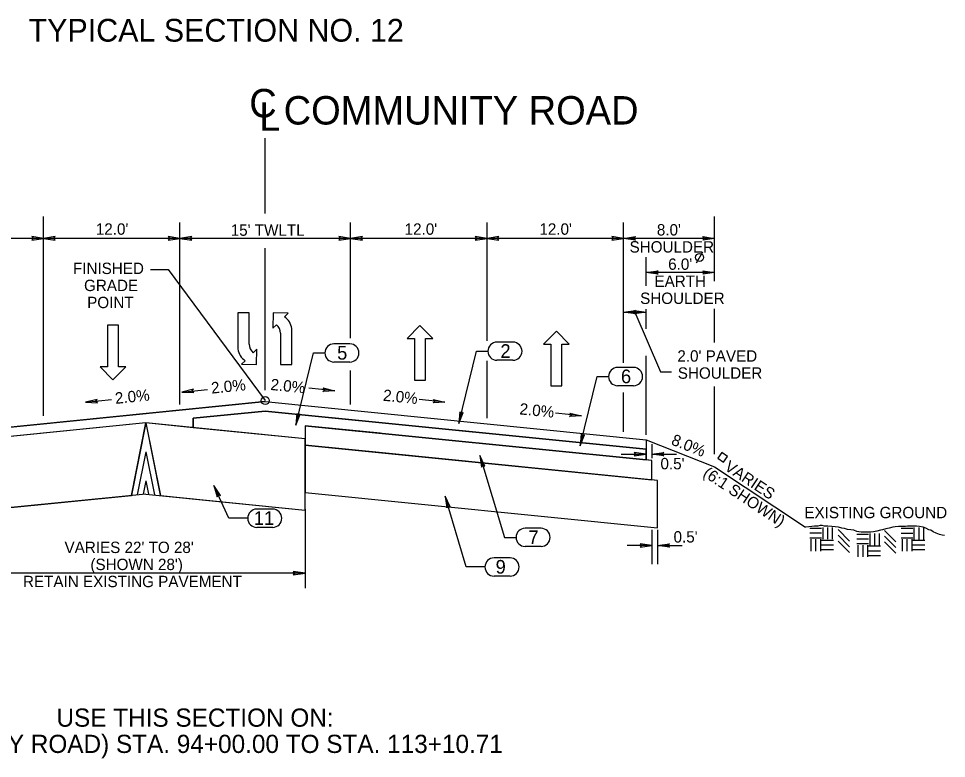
# Model space of a CAD drawing. Extents: x 2003207 to 2014043, y 843846 to 860154.
# Drawn here: x 2013870.6 to 2013952.2, y 844709.9 to 844774.9 of the extents above; entities that cross this region are included whole.
import ezdxf

# ---------------------------------------------------------------- set-up
doc = ezdxf.new("R2010")
doc.units = 0
for name, color, linetype in [('RD_EX_Road', 7, 'Continuous'), ('RD_EX_Road_txCode', 7, 'Continuous'), ('RD_QTY_Base_Course', 7, 'Continuous'), ('RD_QTY_ConcPave', 7, 'Continuous'), ('RD_QTY_Intermediate', 7, 'Continuous'), ('RD_QTY_PermVeg', 7, 'Continuous'), ('RD_QTY_Surf_Course', 7, 'Continuous'), ('RD_TX_Misc1', 7, 'Continuous'), ('RD_TX_Misc2', 7, 'Continuous'), ('RD_TX_TypSect', 7, 'Continuous'), ('RD_XS_ExGround', 7, 'Continuous')]:
    doc.layers.add(name, color=color, linetype=linetype)

msp = doc.modelspace()

# ---------------------------------------------------------------- linework, layer by layer
at = {"layer": 'RD_EX_Road'}
for p, q in [((2013881.821, 844739.393), (2013867.821, 844737.993)), ((2013880.546, 844733.015), (2013881.821, 844739.393)), ((2013881.821, 844739.393), (2013880.55, 844733.037)), ((2013895.821, 844737.993), (2013881.821, 844739.393)), ((2013881.821, 844739.393), (2013883.097, 844733.015)), ((2013881.821, 844739.393), (2013883.093, 844733.037)), ((2013895.821, 844731.743), (2013895.821, 844737.993)), ((2013881.821, 844736.843), (2013881.069, 844733.08)), ((2013881.821, 844736.843), (2013882.574, 844733.08)), ((2013881.821, 844734.293), (2013881.587, 844733.123)), ((2013881.821, 844734.293), (2013882.056, 844733.123)), ((2013881.821, 844733.143), (2013867.821, 844731.743)), ((2013867.821, 844731.743), (2013880.546, 844733.015)), ((2013881.821, 844733.143), (2013895.821, 844731.743)), ((2013883.097, 844733.015), (2013895.821, 844731.743))]:
    msp.add_line(p, q, dxfattribs=at)
at = {"layer": 'RD_EX_Road_txCode'}
msp.add_lwpolyline([(2013932.122, 844736.29), (2013932.622, 844735.959), (2013932.954, 844736.459), (2013932.454, 844736.79)], close=True, dxfattribs=at)
msp.add_circle((2013892.321, 844741.359), 0.35, dxfattribs=at)
at = {"layer": 'RD_QTY_Base_Course'}
for p, q in [((2013902.421, 844738.485), (2013895.821, 844739.145)), ((2013895.821, 844739.145), (2013895.821, 844739.115)), ((2013902.421, 844738.47), (2013902.421, 844738.485)), ((2013926.321, 844736.083), (2013902.421, 844738.47)), ((2013895.821, 844737.441), (2013926.321, 844734.391)), ((2013902.921, 844736.731), (2013895.821, 844737.441)), ((2013895.821, 844737.441), (2013895.821, 844734.676)), ((2013926.821, 844734.341), (2013902.921, 844736.731)), ((2013926.321, 844734.391), (2013926.321, 844736.083)), ((2013895.821, 844734.676), (2013895.821, 844734.192)), ((2013895.821, 844734.192), (2013895.821, 844733.274)), ((2013926.821, 844734.341), (2013926.321, 844734.391)), ((2013926.821, 844730.174), (2013926.821, 844734.341)), ((2013926.821, 844730.174), (2013926.821, 844734.341)), ((2013895.821, 844733.274), (2013926.821, 844730.174)), ((2013895.821, 844733.274), (2013926.821, 844730.174))]:
    msp.add_line(p, q, dxfattribs=at)
msp.add_lwpolyline([(2013895.821, 844739.115), (2013895.821, 844738.282), (2013895.821, 844737.441)], dxfattribs=at)
at = {"layer": 'RD_QTY_ConcPave'}
for p, q in [((2013895.821, 844737.441), (2013926.321, 844734.391)), ((2013926.321, 844736.083), (2013925.821, 844736.145)), ((2013926.321, 844734.391), (2013926.321, 844736.083))]:
    msp.add_line(p, q, dxfattribs=at)
at = {"layer": 'RD_QTY_Intermediate'}
for p, q in [((2013895.821, 844739.145), (2013925.821, 844736.145)), ((2013925.821, 844736.145), (2013925.821, 844737.092))]:
    msp.add_line(p, q, dxfattribs=at)
msp.add_lwpolyline([(2013895.821, 844737.993), (2013885.99, 844738.976), (2013885.99, 844739.809), (2013892.321, 844740.442), (2013895.821, 844740.092), (2013925.821, 844737.092), (2013925.821, 844736.145), (2013895.821, 844739.145)], close=True, dxfattribs=at)
at = {"layer": 'RD_QTY_PermVeg'}
for p, q in [((2013925.821, 844737.926), (2013931.821, 844735.526)), ((2013931.821, 844735.526), (2013939.821, 844730.224))]:
    msp.add_line(p, q, dxfattribs=at)
at = {"layer": 'RD_QTY_Surf_Course'}
for p, q in [((2013892.321, 844741.276), (2013858.821, 844737.926)), ((2013892.321, 844741.276), (2013925.821, 844737.926)), ((2013892.321, 844740.442), (2013925.821, 844737.092)), ((2013925.821, 844737.926), (2013925.821, 844737.092))]:
    msp.add_line(p, q, dxfattribs=at)
msp.add_lwpolyline([(2013858.821, 844737.926), (2013892.321, 844741.276), (2013925.821, 844737.926), (2013925.821, 844737.092), (2013892.321, 844740.442), (2013885.99, 844739.809), (2013885.99, 844738.976), (2013881.821, 844739.393), (2013858.821, 844737.092)], close=True, dxfattribs=at)
at = {"layer": 'RD_TX_Misc2'}
for p, q in [((2013899.759, 844746.35), (2013898.359, 844746.35)), ((2013914.094, 844746.5), (2013912.694, 844746.5)), ((2013899.759, 844744.75), (2013898.359, 844744.75)), ((2013914.094, 844744.9), (2013912.694, 844744.9)), ((2013924.703, 844744.272), (2013923.303, 844744.272)), ((2013924.703, 844742.672), (2013923.303, 844742.672)), ((2013892.975, 844731.819), (2013891.575, 844731.819)), ((2013892.975, 844730.219), (2013891.575, 844730.219)), ((2013916.57, 844730.134), (2013915.17, 844730.134)), ((2013916.57, 844728.534), (2013915.17, 844728.534)), ((2013913.839, 844727.535), (2013912.439, 844727.535)), ((2013913.839, 844725.935), (2013912.439, 844725.935))]:
    msp.add_line(p, q, dxfattribs=at)
for centre, start, end in [((2013898.359, 844745.55), 90, 270), ((2013899.759, 844745.55), 270, 90), ((2013912.694, 844745.7), 90, 270), ((2013914.094, 844745.7), 270, 90), ((2013923.303, 844743.472), 90, 270), ((2013924.703, 844743.472), 270, 90), ((2013891.575, 844731.019), 90, 270), ((2013892.975, 844731.019), 270, 90), ((2013915.17, 844729.334), 90, 270), ((2013916.57, 844729.334), 270, 90), ((2013912.439, 844726.735), 90, 270), ((2013913.839, 844726.735), 270, 90)]:
    msp.add_arc(centre, 0.8, start, end, dxfattribs=at)
at = {"layer": 'RD_TX_TypSect'}
for p, q in [((2013892.321, 844757.819), (2013892.321, 844764.438)), ((2013872.821, 844740.014), (2013872.821, 844757.53)), ((2013884.821, 844741.026), (2013884.821, 844757.013)), ((2013899.821, 844746.845), (2013899.821, 844757.013)), ((2013911.821, 844746.604), (2013911.821, 844757.013)), ((2013923.821, 844744.965), (2013923.821, 844757.013)), ((2013923.821, 844744.678), (2013923.821, 844757.013)), ((2013931.821, 844751.872), (2013931.821, 844757.53)), ((2013872.821, 844755.623), (2013860.821, 844755.623)), ((2013884.821, 844755.623), (2013872.821, 844755.623)), ((2013899.821, 844755.623), (2013884.821, 844755.623)), ((2013911.821, 844755.623), (2013899.821, 844755.623)), ((2013923.821, 844755.623), (2013911.821, 844755.623)), ((2013931.821, 844755.623), (2013923.821, 844755.623)), ((2013892.321, 844742.276), (2013892.321, 844754.769)), ((2013930.225, 844753.479), (2013930.791, 844754.423)), ((2013925.821, 844751.438), (2013925.821, 844753.977)), ((2013931.821, 844752.623), (2013925.821, 844752.623)), ((2013889.918, 844749.064), (2013889.918, 844745.899)), ((2013890.908, 844749.064), (2013889.918, 844749.064)), ((2013890.908, 844746.319), (2013890.908, 844749.064)), ((2013893.008, 844749.064), (2013892.993, 844747.714)), ((2013894.328, 844749.049), (2013893.008, 844749.064)), ((2013894.013, 844748.734), (2013894.328, 844749.049)), ((2013923.821, 844749.123), (2013925.821, 844749.123)), ((2013925.821, 844747.665), (2013925.821, 844749.395)), ((2013931.821, 844746.466), (2013931.821, 844749.423)), ((2013892.993, 844747.714), (2013893.308, 844748.029)), ((2013893.653, 844747.279), (2013893.653, 844744.534)), ((2013894.643, 844744.534), (2013894.643, 844747.699)), ((2013891.568, 844745.884), (2013891.253, 844745.569)), ((2013891.553, 844744.534), (2013891.568, 844745.884)), ((2013890.548, 844744.864), (2013890.233, 844744.549)), ((2013911.821, 844739.826), (2013911.821, 844744.847)), ((2013925.821, 844738.351), (2013925.821, 844745.282)), ((2013890.233, 844744.549), (2013891.553, 844744.534)), ((2013893.653, 844744.534), (2013894.643, 844744.534)), ((2013899.821, 844741.026), (2013899.821, 844744.014)), ((2013884.978, 844742.115), (2013887.255, 844742.343)), ((2013898.441, 844742.22), (2013896.165, 844742.448)), ((2013931.821, 844736.638), (2013931.821, 844742.603)), ((2013876.526, 844741.215), (2013878.803, 844741.443)), ((2013908.117, 844741.215), (2013905.84, 844741.443)), ((2013923.821, 844739.826), (2013923.821, 844742.076)), ((2013923.821, 844738.626), (2013923.821, 844741.985)), ((2013920.117, 844740.015), (2013917.84, 844740.243)), ((2013926.321, 844737.52), (2013926.321, 844736.291)), ((2013923.624, 844736.66), (2013925.791, 844736.66)), ((2013926.321, 844736.66), (2013928.489, 844736.66)), ((2013895.821, 844731.804), (2013895.821, 844724.868)), ((2013926.321, 844729.991), (2013926.321, 844726.996)), ((2013926.821, 844729.991), (2013926.821, 844726.996)), ((2013926.321, 844728.619), (2013924.154, 844728.619)), ((2013926.821, 844728.619), (2013928.989, 844728.619)), ((2013895.821, 844726.187), (2013867.821, 844726.187))]:
    msp.add_line(p, q, dxfattribs=at)
for points in [[(2013872.821, 844755.623), (2013871.783, 844755.773), (2013871.943, 844755.623), (2013871.783, 844755.473)], [(2013872.821, 844755.623), (2013873.86, 844755.473), (2013873.7, 844755.623), (2013873.86, 844755.773)], [(2013884.821, 844755.623), (2013883.783, 844755.773), (2013883.943, 844755.623), (2013883.783, 844755.473)], [(2013884.821, 844755.623), (2013885.86, 844755.473), (2013885.7, 844755.623), (2013885.86, 844755.773)], [(2013899.821, 844755.623), (2013898.783, 844755.773), (2013898.943, 844755.623), (2013898.783, 844755.473)], [(2013899.821, 844755.623), (2013900.86, 844755.473), (2013900.7, 844755.623), (2013900.86, 844755.773)], [(2013911.821, 844755.623), (2013910.783, 844755.773), (2013910.943, 844755.623), (2013910.783, 844755.473)], [(2013911.821, 844755.623), (2013912.86, 844755.473), (2013912.7, 844755.623), (2013912.86, 844755.773)], [(2013923.821, 844755.623), (2013922.783, 844755.773), (2013922.943, 844755.623), (2013922.783, 844755.473)], [(2013923.821, 844755.623), (2013924.86, 844755.773), (2013924.7, 844755.623), (2013924.86, 844755.473)], [(2013931.821, 844755.623), (2013930.783, 844755.473), (2013930.943, 844755.623), (2013930.783, 844755.773)], [(2013925.821, 844752.623), (2013926.86, 844752.773), (2013926.7, 844752.623), (2013926.86, 844752.473)], [(2013931.821, 844752.623), (2013930.783, 844752.473), (2013930.943, 844752.623), (2013930.783, 844752.773)], [(2013923.821, 844749.123), (2013924.86, 844749.273), (2013924.7, 844749.123), (2013924.86, 844748.973)], [(2013925.821, 844749.123), (2013924.783, 844748.973), (2013924.943, 844749.123), (2013924.783, 844749.273)], [(2013879.403, 844747.998), (2013878.443, 844747.998), (2013878.443, 844744.33), (2013877.792, 844744.33), (2013878.923, 844743.198), (2013880.055, 844744.33), (2013879.403, 844744.33)], [(2013905.443, 844743.151), (2013906.403, 844743.151), (2013906.403, 844746.819), (2013907.055, 844746.819), (2013905.923, 844747.951), (2013904.792, 844746.819), (2013905.443, 844746.819)], [(2013917.443, 844742.651), (2013918.403, 844742.651), (2013918.403, 844746.319), (2013919.055, 844746.319), (2013917.923, 844747.451), (2013916.792, 844746.319), (2013917.443, 844746.319)], [(2013884.978, 844742.115), (2013886.026, 844742.069), (2013885.852, 844742.203), (2013885.996, 844742.368)], [(2013898.441, 844742.22), (2013897.393, 844742.174), (2013897.567, 844742.308), (2013897.423, 844742.473)], [(2013876.526, 844741.215), (2013877.574, 844741.169), (2013877.4, 844741.302), (2013877.544, 844741.467)], [(2013908.117, 844741.215), (2013907.069, 844741.169), (2013907.243, 844741.302), (2013907.098, 844741.467)], [(2013894.994, 844739.192), (2013895.387, 844740.166), (2013895.203, 844740.046), (2013895.096, 844740.237)], [(2013909.329, 844739.343), (2013909.721, 844740.316), (2013909.538, 844740.196), (2013909.43, 844740.387)], [(2013920.117, 844740.015), (2013919.069, 844739.969), (2013919.243, 844740.102), (2013919.098, 844740.267)], [(2013920.004, 844737.386), (2013920.397, 844738.359), (2013920.213, 844738.239), (2013920.105, 844738.43)], [(2013911.191, 844736.543), (2013911.347, 844735.505), (2013911.444, 844735.701), (2013911.634, 844735.591)], [(2013925.791, 844736.66), (2013924.753, 844736.81), (2013924.913, 844736.66), (2013924.753, 844736.51)], [(2013926.321, 844736.66), (2013927.36, 844736.81), (2013927.2, 844736.66), (2013927.36, 844736.51)], [(2013887.812, 844733.911), (2013888.097, 844732.901), (2013888.169, 844733.109), (2013888.371, 844733.023)], [(2013908.131, 844732.974), (2013908.281, 844731.936), (2013908.38, 844732.132), (2013908.569, 844732.021)], [(2013926.321, 844728.619), (2013925.283, 844728.769), (2013925.443, 844728.619), (2013925.283, 844728.47)], [(2013926.821, 844728.619), (2013927.86, 844728.769), (2013927.7, 844728.619), (2013927.86, 844728.47)], [(2013895.821, 844726.187), (2013894.783, 844726.336), (2013894.943, 844726.187), (2013894.783, 844726.037)]]:
    msp.add_lwpolyline(points, close=True, dxfattribs=at)
for points in [[(2013882.216, 844752.88), (2013883.785, 844752.88), (2013892.321, 844741.359)], [(2013924.821, 844749.123), (2013927.062, 844743.876), (2013928.049, 844743.876)], [(2013894.994, 844739.192), (2013896.55, 844745.55), (2013897.559, 844745.55)], [(2013909.329, 844739.343), (2013910.885, 844745.7), (2013911.894, 844745.7)], [(2013920.004, 844737.386), (2013921.494, 844743.472), (2013922.503, 844743.472)], [(2013911.191, 844736.543), (2013913.362, 844729.334), (2013914.37, 844729.334)], [(2013890.775, 844731.019), (2013889.109, 844731.019), (2013887.812, 844733.911)], [(2013911.639, 844726.735), (2013909.973, 844726.735), (2013908.131, 844732.974)]]:
    msp.add_lwpolyline(points, dxfattribs=at)
msp.add_circle((2013930.508, 844753.951), 0.35, dxfattribs=at)
for centre, radius, start, end in [((2013893.091, 844747.461), 1.576, 8.67607, 53.98777), ((2013892.676, 844747.282), 0.983, 0, 49.65818), ((2013891.886, 844746.316), 0.983, 180, 229.65817), ((2013891.471, 844746.137), 1.576, 188.67607, 233.98777)]:
    msp.add_arc(centre, radius, start, end, dxfattribs=at)
at = {"layer": 'RD_XS_ExGround'}
for p, q in [((2013941.235, 844730.111), (2013940.193, 844730.111)), ((2013941.331, 844730.208), (2013941.331, 844729.166)), ((2013941.748, 844730.208), (2013941.748, 844729.166)), ((2013942.165, 844730.208), (2013942.165, 844729.166)), ((2013943.687, 844729.017), (2013942.687, 844730.017)), ((2013947.755, 844728.944), (2013946.755, 844729.944)), ((2013949.262, 844730.106), (2013948.22, 844730.106)), ((2013949.358, 844730.203), (2013949.358, 844729.162)), ((2013949.775, 844730.203), (2013949.775, 844729.162)), ((2013950.191, 844730.203), (2013950.191, 844729.162)), ((2013941.235, 844729.694), (2013940.193, 844729.694)), ((2013941.235, 844729.278), (2013940.193, 844729.278)), ((2013940.297, 844729.174), (2013940.297, 844728.132)), ((2013940.714, 844729.174), (2013940.714, 844728.132)), ((2013941.131, 844729.174), (2013941.131, 844728.132)), ((2013943.687, 844728.517), (2013942.687, 844729.517)), ((2013945.371, 844729.593), (2013944.329, 844729.593)), ((2013945.371, 844729.176), (2013944.329, 844729.176)), ((2013945.467, 844729.689), (2013945.467, 844728.648)), ((2013945.884, 844729.689), (2013945.884, 844728.648)), ((2013946.301, 844729.689), (2013946.301, 844728.648)), ((2013947.755, 844728.444), (2013946.755, 844729.444)), ((2013949.262, 844729.69), (2013948.22, 844729.69)), ((2013949.262, 844729.273), (2013948.22, 844729.273)), ((2013948.324, 844729.169), (2013948.324, 844728.127)), ((2013948.741, 844729.169), (2013948.741, 844728.127)), ((2013949.157, 844729.169), (2013949.157, 844728.127)), ((2013942.276, 844729.069), (2013941.235, 844729.069)), ((2013942.276, 844728.653), (2013941.235, 844728.653)), ((2013943.687, 844728.017), (2013942.687, 844729.017)), ((2013945.371, 844728.759), (2013944.329, 844728.759)), ((2013944.434, 844728.655), (2013944.434, 844727.613)), ((2013944.85, 844728.655), (2013944.85, 844727.613)), ((2013945.267, 844728.655), (2013945.267, 844727.613)), ((2013946.413, 844728.551), (2013945.371, 844728.551)), ((2013947.755, 844727.944), (2013946.755, 844728.944)), ((2013950.303, 844729.065), (2013949.262, 844729.065)), ((2013950.303, 844728.648), (2013949.262, 844728.648)), ((2013942.276, 844728.236), (2013941.235, 844728.236)), ((2013946.413, 844728.134), (2013945.371, 844728.134)), ((2013946.413, 844727.718), (2013945.371, 844727.718)), ((2013950.303, 844728.231), (2013949.262, 844728.231))]:
    msp.add_line(p, q, dxfattribs=at)
msp.add_lwpolyline([(2013952.047, 844729.491), (2013951.828, 844729.528), (2013951.608, 844729.601), (2013951.315, 844729.711), (2013951.059, 844729.821), (2013950.839, 844729.967), (2013950.656, 844730.004), (2013950.4, 844730.15), (2013950.18, 844730.224), (2013949.851, 844730.297), (2013949.595, 844730.333), (2013949.302, 844730.333), (2013948.972, 844730.333), (2013948.789, 844730.333), (2013948.606, 844730.297), (2013948.387, 844730.297), (2013948.167, 844730.297), (2013947.984, 844730.297), (2013947.691, 844730.26), (2013947.508, 844730.224), (2013947.179, 844730.15), (2013946.886, 844730.077), (2013946.593, 844730.004), (2013946.41, 844729.967), (2013946.081, 844729.894), (2013945.788, 844729.821), (2013945.568, 844729.784), (2013945.385, 844729.784), (2013945.166, 844729.784), (2013944.946, 844729.784), (2013944.726, 844729.784), (2013944.507, 844729.821), (2013944.324, 844729.857), (2013944.068, 844729.967), (2013943.811, 844730.004), (2013943.518, 844730.04), (2013943.262, 844730.114), (2013943.006, 844730.15), (2013942.713, 844730.224), (2013942.42, 844730.26), (2013942.128, 844730.297), (2013941.798, 844730.333), (2013941.505, 844730.333), (2013941.286, 844730.37), (2013941.103, 844730.37), (2013940.92, 844730.333), (2013940.627, 844730.333), (2013940.371, 844730.297), (2013940.114, 844730.26), (2013939.821, 844730.224)], dxfattribs=at)

# ---------------------------------------------------------------- texts
at = {"layer": 'RD_EX_Road_txCode'}
for s, p in [('USE THIS SECTION ON:', (2013873.958, 844712.693)), ('COMM (S-2885 COMMUNITY ROAD) STA. 94+00.00 TO STA. 113+10.71', (2013842.342, 844710.387))]:
    msp.add_text(s, height=1.6, dxfattribs=at).set_placement(p)
at = {"layer": 'RD_TX_Misc1'}
for s, p in [('C', (2013890.913, 844766.257)), ('L', (2013891.79, 844765.076)), ('COMMUNITY ROAD', (2013893.939, 844765.628))]:
    msp.add_text(s, height=2.5, dxfattribs=at).set_placement(p)
at = {"layer": 'RD_TX_Misc2'}
for s, p in [('2', (2013912.998, 844745.115)), ('5', (2013898.641, 844744.965)), ('6', (2013923.596, 844742.888)), ('11', (2013891.314, 844730.434)), ('7', (2013915.463, 844728.749)), ('9', (2013912.574, 844726.15))]:
    msp.add_text(s, height=1.2, dxfattribs=at).set_placement(p)
at = {"layer": 'RD_TX_TypSect'}
for s, height, p in [('TYPICAL SECTION NO. 12', 2, (2013871.51, 844772.912)), ("12.0'", 1, (2013877.423, 844755.94)), ("15' TWLTL", 1, (2013889.284, 844755.846)), ("12.0'", 1, (2013904.575, 844755.94)), ("12.0'", 1, (2013916.423, 844755.94)), ("8.0'", 1, (2013926.753, 844755.873)), ('SHOULDER', 1, (2013924.353, 844754.373)), ("6.0'", 1, (2013927.747, 844752.855)), ('FINISHED', 1, (2013875.409, 844752.486)), ('GRADE', 1, (2013876.385, 844750.986)), ('EARTH', 1, (2013926.542, 844751.355)), ('POINT', 1, (2013876.661, 844749.486)), ('SHOULDER', 1, (2013925.282, 844749.855)), ("2.0' PAVED", 1, (2013928.554, 844744.783)), ('SHOULDER', 1, (2013928.593, 844743.283)), ("0.5'", 1, (2013927.069, 844735.321)), ('EXISTING GROUND', 1, (2013939.722, 844731.02)), ("0.5'", 1, (2013928.22, 844728.883)), ("VARIES 22' TO 28'", 1, (2013874.67, 844727.961)), ("(SHOWN 28')", 1, (2013876.946, 844726.461)), ('RETAIN EXISTING PAVEMENT', 1, (2013871.017, 844724.961))]:
    msp.add_text(s, height=height, dxfattribs=at).set_placement(p)
for s, rotation, p in [('2.0%', 5.71059, (2013887.611, 844741.969)), ('2.0%', 354.28941, (2013892.744, 844742.299)), ('2.0%', 5.71059, (2013879.159, 844741.068)), ('2.0%', 354.28941, (2013902.64, 844741.353)), ('2.0%', 354.28941, (2013914.64, 844740.153)), ('8.0%', 338.19859, (2013927.944, 844737.524)), ('VARIES', 326.46577, (2013932.617, 844735.319)), ('(6:1 SHOWN)', 326.46577, (2013930.731, 844734.769))]:
    msp.add_text(s, height=1, rotation=rotation, dxfattribs=at).set_placement(p)

doc.saveas('drawing.dxf')
